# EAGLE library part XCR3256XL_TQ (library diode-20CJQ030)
Xilinx XCR3256XL 256 Macrocell CPLD Description: The XCR3256XL is a 3.3V, 256 macrocell CPLD targeted at power sensitive designs that require leading edge programmable logic solutions. A total of 16 function blocks provide 6,000 usable gates. Pin-to-pin propagation delays are 7.5 ns with a maximum system frequency of 154 MHz. Features Low power 3.3V 256 macrocell CPLD 7.5 ns pin-to-pin logic delays System frequencies up to 154 MHz 256 macrocells with 6,000 usable gates Available in small footprint packages - 144-pin TQFP (120 user I/O pins) - 208-pin PQFP (164 user I/O) - 256-ball FBGA (164 user I/O) - 280-ball CS BGA (164 user I/O) Optimized for 3.3V systems - Ultra low power operation - 5V tolerant I/O pins with 3.3V core supply - Advanced 0.35 micron five layer metal EEPROM process - Fast Zero Power? (FZP) CMOS design technology - 3.3V PCI electrical specification compatible outputs (no internal clamp diode on any input or I/O) Advanced system features - In-system programming - Input registers - Predictable timing model - Up to 23 clocks available per function block - Excellent pin retention during design changes - Full IEEE Standard 1149.1 boundary-scan (JTAG) - Four global clocks - Eight product term control terms per function block Fast ISP programming times Port Enable pin for additional I/O 2.7V to 3.6V supply voltage at industrial grade voltage range Programmable slew rate control per output Security bit prevents unauthorized access Refer to XPLA3 family data sheet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
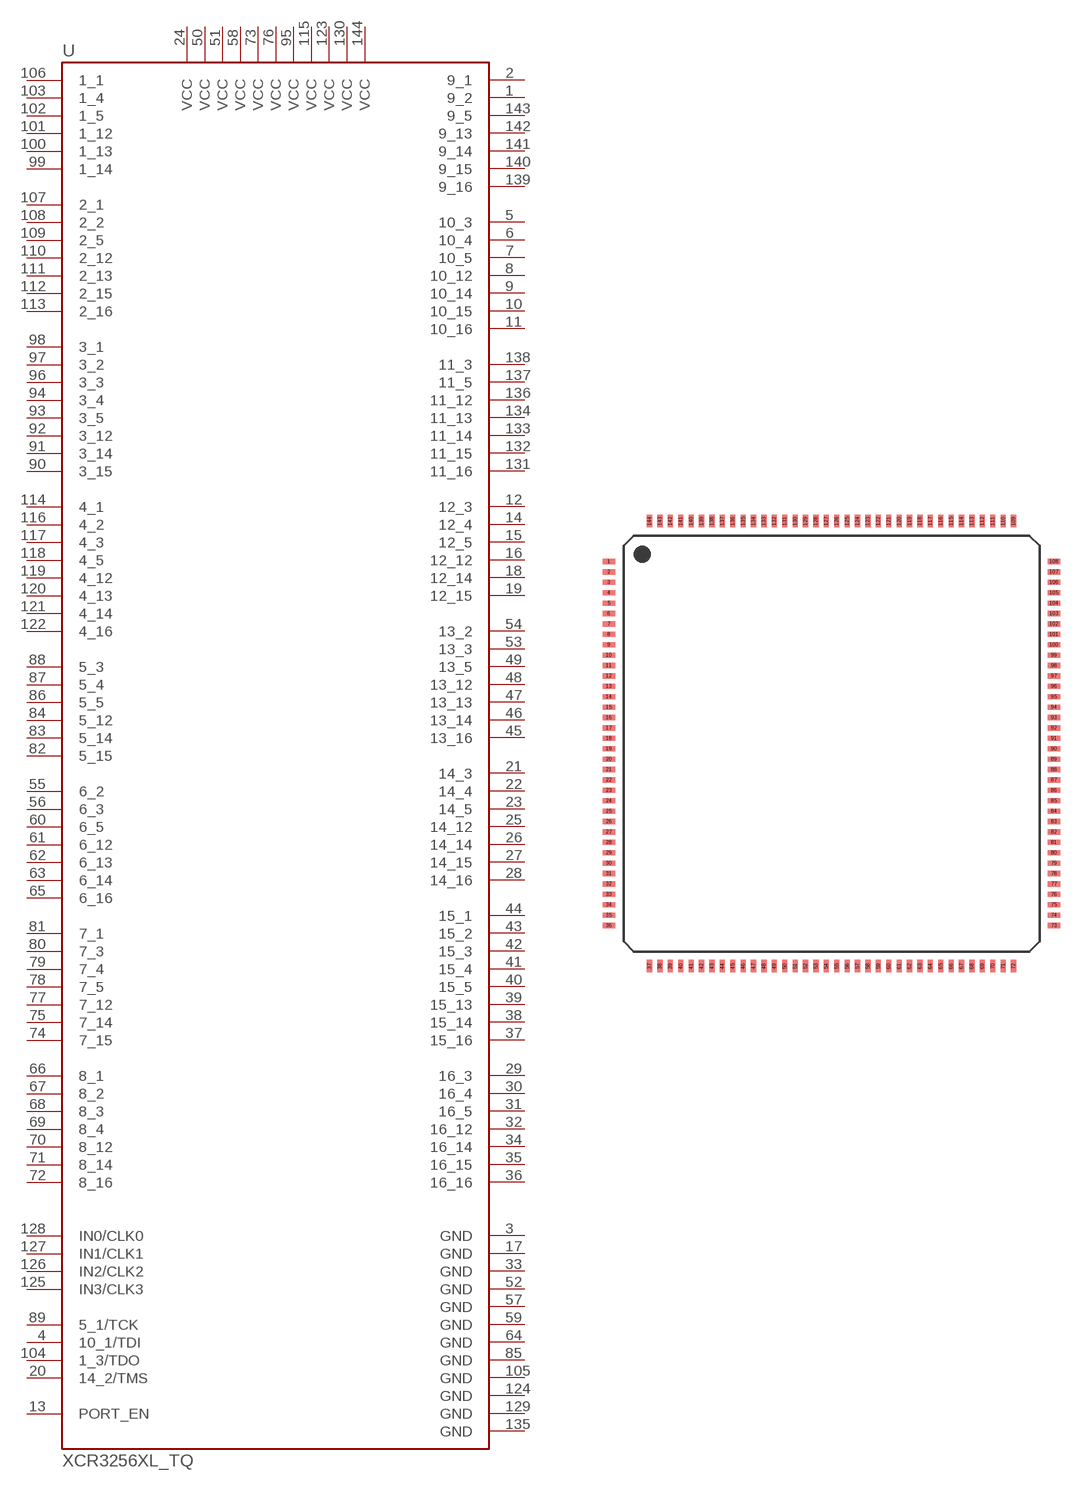
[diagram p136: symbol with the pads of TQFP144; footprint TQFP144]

Designator prefix U

## XCR3256XL_TQ  [TQFP144]
1  9_2
2  9_1
3  GND  pwr
4  10_1/TDI
5  10_3
6  10_4
7  10_5
8  10_12
9  10_14
10  10_15
11  10_16
12  12_3
13  PORT_EN  in
14  12_4
15  12_5
16  12_12
17  GND  pwr
18  12_14
19  12_15
20  14_2/TMS
21  14_3
22  14_4
23  14_5
24  VCC  pwr
25  14_12
26  14_14
27  14_15
28  14_16
29  16_3
30  16_4
31  16_5
32  16_12
33  GND  pwr
34  16_14
35  16_15
36  16_16
37  15_16
38  15_14
39  15_13
40  15_5
41  15_4
42  15_3
43  15_2
44  15_1
45  13_16
46  13_14
47  13_13
48  13_12
49  13_5
50  VCC  pwr
51  VCC  pwr
52  GND  pwr
53  13_3
54  13_2
55  6_2
56  6_3
57  GND  pwr
58  VCC  pwr
59  GND  pwr
60  6_5
61  6_12
62  6_13
63  6_14
64  GND  pwr
65  6_16
66  8_1
67  8_2
68  8_3
69  8_4
70  8_12
71  8_14
72  8_16
73  VCC  pwr
74  7_15
75  7_14
76  VCC  pwr
77  7_12
78  7_5
79  7_4
80  7_3
81  7_1
82  5_15
83  5_14
84  5_12
85  GND  pwr
86  5_5
87  5_4
88  5_3
89  5_1/TCK
90  3_15
91  3_14
92  3_12
93  3_5
94  3_4
95  VCC  pwr
96  3_3
97  3_2
98  3_1
99  1_14
100  1_13
101  1_12
102  1_5
103  1_4
104  1_3/TDO
105  GND  pwr
106  1_1
107  2_1
108  2_2
109  2_5
110  2_12
111  2_13
112  2_15
113  2_16
114  4_1
115  VCC  pwr
116  4_2
117  4_3
118  4_5
119  4_12
120  4_13
121  4_14
122  4_16
123  VCC  pwr
124  GND  pwr
125  IN3/CLK3
126  IN2/CLK2
127  IN1/CLK1
128  IN0/CLK0
129  GND  pwr
130  VCC  pwr
131  11_16
132  11_15
133  11_14
134  11_13
135  GND  pwr
136  11_12
137  11_5
138  11_3
139  9_16
140  9_15
141  9_14
142  9_13
143  9_5
144  VCC  pwr

## Footprint TQFP144 (pad centres in mm)
TQFP (TQ/TQG 100, 144, 176 Pin) Packages and Heat Sink TQFP (HT/HTG 100, 144, 176 Pin) Packages - Pitch: 0.5 mm - Pad-length : 0.6mm - Pad-Width : 0.22mm (0.25) Please send any comments to: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
smd 0.6 x 0.25: 1 -10.7,8.75; 2 -10.7,8.25; 3 -10.7,7.75; 4 -10.7,7.25; 5 -10.7,6.75; 6 -10.7,6.25; 7 -10.7,5.75; 8 -10.7,5.25; 9 -10.7,4.75; 10 -10.7,4.25; 11 -10.7,3.75; 12 -10.7,3.25; 13 -10.7,2.75; 14 -10.7,2.25; 15 -10.7,1.75; 16 -10.7,1.25; 17 -10.7,0.75; 18 -10.7,0.25; 19 -10.7,-0.25; 20 -10.7,-0.75; 21 -10.7,-1.25; 22 -10.7,-1.75; 23 -10.7,-2.25; 24 -10.7,-2.75; 25 -10.7,-3.25; 26 -10.7,-3.75; 27 -10.7,-4.25; 28 -10.7,-4.75; 29 -10.7,-5.25; 30 -10.7,-5.75; 31 -10.7,-6.25; 32 -10.7,-6.75; 33 -10.7,-7.25; 34 -10.7,-7.75; 35 -10.7,-8.25; 36 -10.7,-8.75; 73 10.7,-8.75; 74 10.7,-8.25; 75 10.7,-7.75; 76 10.7,-7.25; 77 10.7,-6.75; 78 10.7,-6.25; 79 10.7,-5.75; 80 10.7,-5.25; 81 10.7,-4.75; 82 10.7,-4.25; 83 10.7,-3.75; 84 10.7,-3.25; 85 10.7,-2.75; 86 10.7,-2.25; 87 10.7,-1.75; 88 10.7,-1.25; 89 10.7,-0.75; 90 10.7,-0.25; 91 10.7,0.25; 92 10.7,0.75; 93 10.7,1.25; 94 10.7,1.75; 95 10.7,2.25; 96 10.7,2.75; 97 10.7,3.25; 98 10.7,3.75; 99 10.7,4.25; 100 10.7,4.75; 101 10.7,5.25; 102 10.7,5.75; 103 10.7,6.25; 104 10.7,6.75; 105 10.7,7.25; 106 10.7,7.75; 107 10.7,8.25; 108 10.7,8.75
smd 0.25 x 0.6: 37 -8.75,-10.7; 38 -8.25,-10.7; 39 -7.75,-10.7; 40 -7.25,-10.7; 41 -6.75,-10.7; 42 -6.25,-10.7; 43 -5.75,-10.7; 44 -5.25,-10.7; 45 -4.75,-10.7; 46 -4.25,-10.7; 47 -3.75,-10.7; 48 -3.25,-10.7; 49 -2.75,-10.7; 50 -2.25,-10.7; 51 -1.75,-10.7; 52 -1.25,-10.7; 53 -0.75,-10.7; 54 -0.25,-10.7; 55 0.25,-10.7; 56 0.75,-10.7; 57 1.25,-10.7; 58 1.75,-10.7; 59 2.25,-10.7; 60 2.75,-10.7; 61 3.25,-10.7; 62 3.75,-10.7; 63 4.25,-10.7; 64 4.75,-10.7; 65 5.25,-10.7; 66 5.75,-10.7; 67 6.25,-10.7; 68 6.75,-10.7; 69 7.25,-10.7; 70 7.75,-10.7; 71 8.25,-10.7; 72 8.75,-10.7; 109 8.75,10.7; 110 8.25,10.7; 111 7.75,10.7; 112 7.25,10.7; 113 6.75,10.7; 114 6.25,10.7; 115 5.75,10.7; 116 5.25,10.7; 117 4.75,10.7; 118 4.25,10.7; 119 3.75,10.7; 120 3.25,10.7; 121 2.75,10.7; 122 2.25,10.7; 123 1.75,10.7; 124 1.25,10.7; 125 0.75,10.7; 126 0.25,10.7; 127 -0.25,10.7; 128 -0.75,10.7; 129 -1.25,10.7; 130 -1.75,10.7; 131 -2.25,10.7; 132 -2.75,10.7; 133 -3.25,10.7; 134 -3.75,10.7; 135 -4.25,10.7; 136 -4.75,10.7; 137 -5.25,10.7; 138 -5.75,10.7; 139 -6.25,10.7; 140 -6.75,10.7; 141 -7.25,10.7; 142 -7.75,10.7; 143 -8.25,10.7; 144 -8.75,10.7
